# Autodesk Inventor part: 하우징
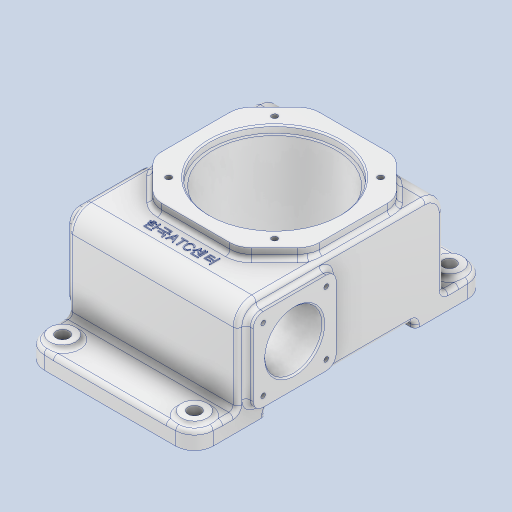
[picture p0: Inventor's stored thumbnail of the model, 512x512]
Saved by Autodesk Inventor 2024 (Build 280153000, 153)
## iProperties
Created: 2026-02
Part Number: 하우징
Material: 알루미늄 6061
Document SubType Name: Modeling
Designer: 2-10
Density: 2.7 g/cm^3
Appearance: 알루미늄 - 평지
Author: 2-10
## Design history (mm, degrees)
sketch "스케치2"
  geometry: L1 (-59, -37.5)-(59, -37.5); L2 (59, -37.5)-(59, 37.5); L3 (59, 37.5)-(-59, 37.5); L4 (-59, 37.5)-(-59, -37.5); L5 (-59, -37.5)-(59, 37.5); L6 (59, -37.5)-(-59, 37.5); 1 further point
  constraints: 12 end point, 2 midpoint, 2 parallel, 1 horizontal, 1 perpendicular
  dimensions: "d4" = 118 distance of L1.start L1.end; "d5" = 75 distance of L1.end L2.end
extrude "돌출2" new body sketch "스케치2" stored distance "d6" = 144; taper "d7" = 0 deg
sketch "스케치3"
  geometry: L1 (118, 0)-(118, -144) reference; L2 (0, 0)-(118, 0) reference; L3 (0, -144)-(0, 0) reference; L4 (118, -144)-(0, -144) reference; L5 (0, 30)-(118, 30); L6 (118, 30)-(118, -174); L7 (118, -174)-(0, -174); L8 (0, -174)-(0, 30); 7 further points
  constraints: 8 end point, 2 midpoint, 2 parallel, 1 horizontal, 1 perpendicular, 1 vertical alignment
  dimensions: "d8" = 204 distance of L5.end L6.end; "d9" = 30 distance between parallel lines of L7 L4; "d10" = 118 distance of L5.start L5.end
extrude "돌출3" join sketch "스케치3" distance "d11" = 12; taper "d12" = 0 deg
fillet "모깎기1" dims "d34" = 13
sketch "스케치4"
  geometry: L1 (4, 30)-(114, 30); L2 (114, 30)-(114, 140); L3 (114, 140)-(4, 140); L4 (4, 140)-(4, 30); L5 (4, 30)-(114, 140); L6 (114, 30)-(4, 140); A1 r 13 centre (105, -17) between (105, -30) and (118, -17) reference; 3 further points
  constraints: 12 end point, 2 midpoint, 2 parallel, 1 horizontal, 1 perpendicular, 1 vertical alignment
  dimensions: "d13" = 110 distance of L2.end L3.end; "d14" = 110 distance of L1.end L2.end; "d51" = 102 vertical distance of A1.centre point (59, 85)
extrude "돌출4" join sketch "스케치4" distance "d15" = 7; taper "d16" = 0 deg
chamfer "모따기1" distance "d17" = 25; stored, may be unused: second distance "d18" = 2, angle "d19" = 45 deg
sketch "스케치5"
  geometry: L1 (4, 115)-(4, 55) reference; C1 r 45 at (59, 85); 2 further points
  constraints: 1 centre point, 1 horizontal alignment, 1 midpoint, 1 vertical alignment
  dimensions: "d52" = 90 diameter of C1
extrude "돌출5" cut sketch "스케치5" distance "d21" = 5; taper "d22" = 0 deg
sketch "스케치6"
  geometry: L1 (39.5, -13)-(-26.5, -13); L2 (39.5, 30)-(-18.5, 30); L3 (-21.5, 27)-(-21.5, 18); L4 (-21.5, 18)-(-15.5, 12); L5 (-15.5, 12)-(-15.5, 7); L6 (-15.5, 7)-(-25, 7); L7 (-26.5, 5.5)-(-26.5, -13); L8 (39.5, 30)-(39.5, -13); L9 (39.5, 32)-(39.5, -58) reference; A1 r 1.5 centre (-25, 5.5) between (-25, 7) and (-26.5, 5.5); A2 r 3 centre (-18.5, 27) between (-18.5, 30) and (-21.5, 27); 4 further points
  constraints: 16 end point, 4 point on circle, 4 point on line, 4 tangent, 3 vertical, 2 centre point, 2 horizontal, 2 perpendicular, 1 coincident, 1 midpoint, 1 vertical alignment
  dimensions: "d24" = 86 diameter of L2 L1; "d25" = 40 diameter of L6 L1; "d26" = 45 deg angle of L1 L4; "d27" = 50 diameter of L4.end L1; "d28" = 6 distance between parallel lines of L5 L3; "d29" = 11 distance between parallel lines of L7 L5; "d30" = 1.5 radius of A1; "d31" = 61 distance of L2.start point (-21.5, 30); "d33" = 3 radius of A2
revolve "회전1" sketch "스케치6" stored, may be unused: angle "d32" = 90 deg
sketch "스케치8"
  geometry: C1 r 9 at (13, 161); C2 r 9 at (105, 161); C3 r 9 at (13, -17); C4 r 9 at (105, -17); A1 r 13 centre (13, 161) between (13, 174) and (0, 161) reference; A2 r 13 centre (105, 161) between (118, 161) and (105, 174) reference; A3 r 13 centre (13, -17) between (0, -17) and (13, -30) reference; A4 r 13 centre (105, -17) between (105, -30) and (118, -17) reference; 1 further point
  constraints: 4 centre point, 4 coincident, 3 equal radius
  dimensions: "d35" = 18 diameter of C1
extrude "돌출6" join sketch "스케치8" distance "d36" = 3; taper "d37" = 0 deg
sketch "스케치9"
  geometry: C1 r 9 at (0, 0) reference; C2 r 9 at (92, 0) reference; C3 r 9 at (0, -178) reference; C4 r 9 at (92, -178) reference; 5 further points
  constraints: 4 coincident
hole "구멍1" sketch "스케치9" at (0, 0), (92, 0), (0, -178), (92, -178) diameter "d38" = 9; stored, may be unused: countersink angle "d42" = 90 deg, drill point angle "d44" = 118 deg; dims "d39" = 6, "d40" = 4, "d41" = 2, "d43" = 8
sketch "스케치10"
  geometry: L1 (-17, -75)-(161, -75) reference; L2 (80, -64)-(138, -64); L3 (138, -64)-(138, -6); L4 (138, -6)-(80, -6); L5 (80, -6)-(80, -64); L6 (80, -64)-(138, -6); L7 (138, -64)-(80, -6); L8 (165.5, -75)-(156.5, -75) reference; L9 (156.5, -60)-(165.5, -60) reference; L10 (29, 7)-(89, 7) reference; 4 further points
  constraints: 12 end point, 4 midpoint, 2 parallel, 1 horizontal, 1 perpendicular
  dimensions: "d45" = 40 distance from line of L1 point (109, -35); "d46" = 58 distance of L3.end L4.end; "d47" = 58 distance of L2.end L3.end; "d50" = 52 horizontal distance of point (109, -35) point (161, -60); "d83" = 50 horizontal distance of point (109, -35) point (59, 7) (derived)
extrude "돌출7" join sketch "스케치10" distance "d53" = 5; taper "d54" = 0 deg
sketch "스케치12"
  geometry: L1 (138, -6)-(80, -6) reference; L2 (80, -6)-(80, -64) reference; C1 r 20 at (109, -35); 3 further points
  constraints: 2 midpoint, 1 centre point, 1 horizontal alignment, 1 vertical alignment
  dimensions: "d55" = 40 diameter of C1
extrude "돌출8" cut sketch "스케치12" extent not by distance; stored distance "d56" = 0; taper "d57" = 0 deg
sketch "스케치13"
  geometry: L1 (-17, -75)-(161, -75) reference; L2 (20, -70)-(124, -70); L3 (124, -70)-(124, -75); L4 (124, -75)-(20, -75); L5 (20, -75)-(20, -70); L6 (174, -75)-(174, -63) reference; L7 (-30, -63)-(-30, -75) reference; 1 further point
  constraints: 8 end point, 2 parallel, 1 horizontal, 1 perpendicular, 1 point on line
  dimensions: "d58" = 50 distance between parallel lines of L3 L6; "d59" = 50 distance between parallel lines of L5 L7; "d60" = 5 distance between parallel lines of L4 L2
extrude "돌출9" cut sketch "스케치13" extent not by distance; stored distance "d61" = 0; taper "d62" = 0 deg
sketch "스케치14"
  geometry: L1 (87, -57)-(131, -57); L2 (131, -57)-(131, -13); L3 (131, -13)-(87, -13); L4 (87, -13)-(87, -57); L5 (87, -57)-(131, -13); L6 (131, -57)-(87, -13); C1 r 20 at (109, -35) reference; 1 further point
  constraints: 12 end point, 2 midpoint, 2 parallel, 1 horizontal, 1 perpendicular
  dimensions: "d63" = 44 distance of L2.end L3.end; "d64" = 44 distance of L1.end L2.end
hole "구멍2" sketch "스케치14" at (87, -57), (131, -13), (131, -57), (87, -13) diameter "d65" = 3.242; stored, may be unused: countersink angle "d69" = 90 deg, drill point angle "d71" = 118 deg; dims "d66" = 8, "d67" = 4, "d68" = 2, "d70" = 10
fillet "모깎기4" dims "d84" = 7
sketch "스케치15"
  geometry: L1 (22, 122)-(96, 122); L2 (96, 122)-(96, 48); L3 (96, 48)-(22, 48); L4 (22, 48)-(22, 122); L5 (22, 122)-(96, 48); L6 (96, 122)-(22, 48); C1 r 45 at (59, 85) reference; 1 further point
  constraints: 12 end point, 2 midpoint, 2 parallel, 1 horizontal, 1 perpendicular
  dimensions: "d72" = 74 distance of L1.end L2.end; "d73" = 74 distance of L2.end L3.end
hole "구멍3" sketch "스케치15" at (96, 122), (96, 48), (22, 48), (22, 122) diameter "d74" = 4.134; stored, may be unused: countersink angle "d78" = 90 deg, drill point angle "d80" = 118 deg; dims "d75" = 10, "d76" = 4, "d77" = 2, "d79" = 12
fillet "모깎기2" dims "d81" = 13
fillet "모깎기5" dims "d85" = 3
fillet "모깎기6" dims "d86" = 3
fillet "모깎기7" dims "d87" = 3
chamfer "모따기2" distance "d88" = 1; stored, may be unused: second distance "d89" = 2, angle "d90" = 45 deg
node "작업 평면1"
sketch "스케치17"
  geometry: C1 r 46 at (56, 72) reference; 2 further points
  constraints: 1 vertical alignment, 1 other
  dimensions: "d92" = 65 distance of point (56, 7) C1.centre
feature "엠보싱1" sketch "스케치17" dims "d4" = 118, "d5" = 75, "d11" = 12, "d12" = 0, "d93" = 0.5, "d94" = 0
fillet "모깎기9" dims "d96" = 15
fillet "모깎기10" dims "d97" = 3
node "솔리드2"
mirror "미러2"
node "투영된 루프1"
feature "A9D066F2-1C7D-4E18-AEED-F7BC21143FA4" dims "d65" = 3.242, "d66" = 8, "d67" = 4, "d68" = 2, "d69" = 90 deg, "d70" = 10, "d71" = 118 deg
other parameters: "d91" = 46.75
